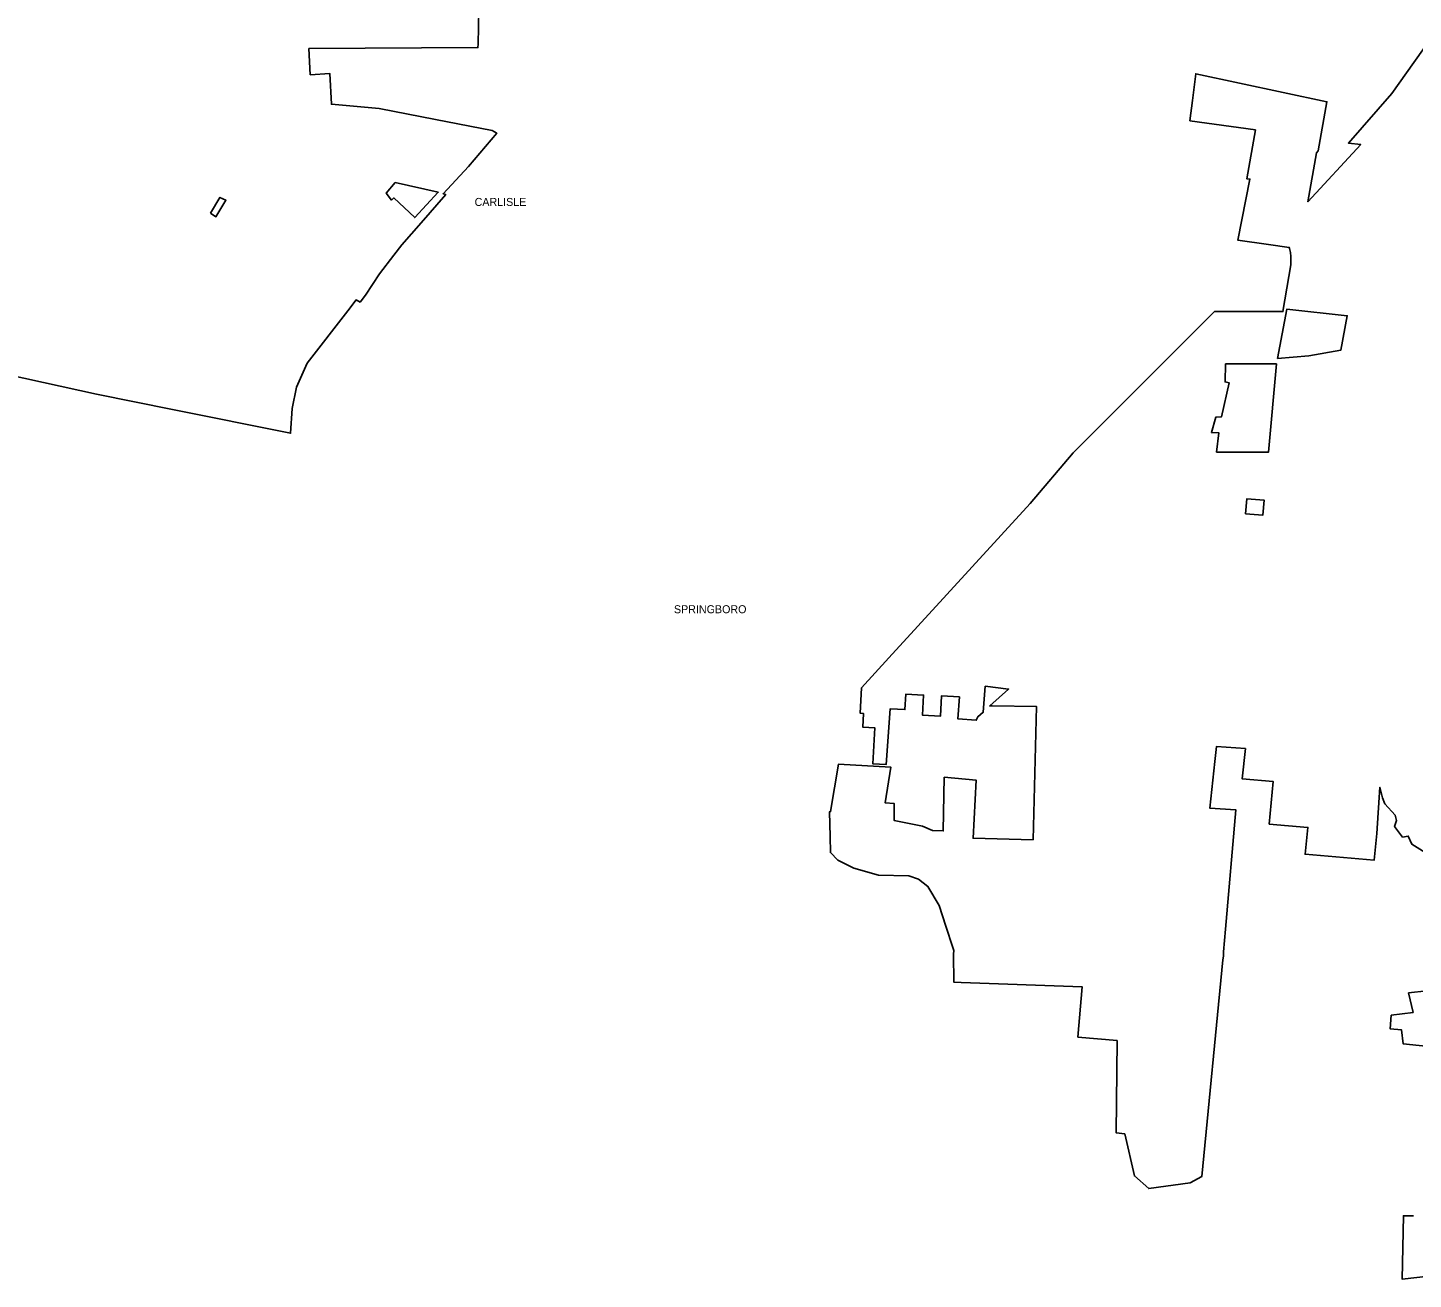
# Model space of a CAD drawing. Extents: x 1312308 to 1684953, y 460642 to 865172.
# Drawn here: x 1455224 to 1476870, y 563008 to 582566 of the extents above; entities that cross this region are included whole.
import ezdxf

# ---------------------------------------------------------------- set-up
doc = ezdxf.new("R2010")
doc.units = 0
doc.layers.add('GM_X_Corporation', color=7, linetype='Continuous')
doc.layers.add('GM_X_Corporation_Text', color=7, linetype='Continuous')

msp = doc.modelspace()

# ---------------------------------------------------------------- linework, layer by layer
at = {"layer": 'GM_X_Corporation'}
for points in [[(1462291, 583939), (1462259, 582309), (1462258, 582256), (1459617, 582239), (1459638, 581832), (1459944, 581848), (1459969, 581369), (1460712, 581304), (1461592, 581133), (1462478, 580961), (1462552, 580917), (1462111, 580397), (1461713, 579971), (1461753, 579959), (1461371, 579519), (1461070, 579173), (1460941, 579013), (1460720, 578719), (1460502, 578384), (1460416, 578278), (1460354, 578312), (1460223, 578144), (1459588, 577325), (1459424, 576949), (1459357, 576615), (1459331, 576228), (1457487, 576599), (1456297, 576842), (1454904, 577147)], [(1477096, 569649), (1476846, 569805), (1476790, 569935), (1476703, 569917), (1476578, 570085), (1476609, 570179), (1476585, 570260), (1476423, 570440), (1476391, 570534), (1476348, 570696), (1476300, 569973), (1476256, 569555), (1475179, 569649), (1475223, 570068), (1474618, 570120), (1474683, 570785), (1474198, 570827), (1474248, 571300), (1473797, 571334), (1473771, 571101), (1473692, 570369), (1474097, 570346), (1473937, 568479), (1473904, 568125), (1473902, 568057), (1473896, 567999), (1473564, 564614), (1473384, 564515), (1472736, 564424), (1472513, 564624), (1472362, 565280), (1472226, 565299), (1472242, 566737), (1471629, 566793), (1471699, 567577), (1469807, 567648), (1469690, 567651), (1469688, 568086), (1469691, 568148), (1469678, 568195), (1469565, 568524), (1469463, 568847), (1469287, 569148), (1469139, 569260), (1468989, 569310), (1468513, 569322), (1468127, 569430), (1467882, 569559), (1467764, 569677), (1467762, 569927), (1467750, 570315), (1467767, 570316), (1467890, 571059), (1468709, 571010), (1468621, 570451), (1468758, 570444), (1468762, 570175), (1469202, 570089), (1469356, 570021), (1469526, 570015), (1469541, 570853), (1470040, 570809), (1469993, 569900), (1470929, 569877), (1470982, 571960), (1470290, 571968), (1470253, 571967), (1470546, 572232), (1470182, 572276), (1470150, 571870), (1470067, 571798), (1470042, 571743), (1469753, 571768), (1469779, 572109), (1469499, 572124), (1469482, 571806), (1469203, 571821), (1469220, 572136), (1468940, 572151), (1468928, 571911), (1468699, 571923), (1468636, 571053), (1468426, 571064), (1468455, 571627), (1468268, 571637), (1468279, 571850), (1468230, 571852), (1468250, 572250), (1468678, 572718), (1470884, 575129), (1471554, 575921), (1473763, 578129), (1474832, 578131), (1474954, 578860), (1474959, 578925), (1474958, 578990), (1474950, 579055), (1474936, 579118), (1474931, 579134), (1474605, 579180), (1474131, 579246), (1474316, 580200), (1474268, 580207), (1474402, 580969), (1473380, 581113), (1473419, 581430), (1473470, 581846), (1475520, 581410), (1475384, 580642), (1475358, 580613), (1475223, 579846), (1476048, 580739), (1475855, 580762), (1476532, 581536), (1477248, 582541)], [(1477762, 566578), (1476710, 566689), (1476684, 566906), (1476508, 566922), (1476526, 567135), (1476866, 567177), (1476795, 567484), (1477080, 567514)], [(1477287, 563080), (1476697, 563008), (1476714, 564002), (1476874, 564002)]]:
    msp.add_lwpolyline(points, dxfattribs=at)
for points in [[(1460966, 580149), (1460825, 579983), (1460908, 579873), (1460941, 579905), (1461270, 579599), (1461638, 579994)], [(1458078, 579670), (1458165, 579612), (1458319, 579869), (1458225, 579915)], [(1474746, 577398), (1475239, 577441), (1475739, 577529), (1475837, 578065), (1474892, 578166)], [(1474734, 577313), (1473937, 577312), (1473929, 577031), (1473995, 577016), (1473875, 576486), (1473784, 576480), (1473717, 576239), (1473832, 576234), (1473797, 575935), (1474608, 575934)], [(1474246, 574968), (1474519, 574947), (1474540, 575181), (1474271, 575206)]]:
    msp.add_lwpolyline(points, close=True, dxfattribs=at)

# ---------------------------------------------------------------- texts
at = {"layer": 'GM_X_Corporation_Text'}
for s, p in [('CARLISLE', (1462205, 579781)), ('SPRINGBORO', (1465319, 573416))]:
    msp.add_text(s, height=125, rotation=0, dxfattribs=at).set_placement(p)

doc.saveas('drawing.dxf')
